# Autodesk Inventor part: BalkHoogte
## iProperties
Created: 2010-03
Part Number: BalkHoogte
Document SubType Name: Modeling
Designer: Ferry
Density: 1 g/cm^3
Author: Ferry
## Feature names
1. Extrusion1
2. Hole1
